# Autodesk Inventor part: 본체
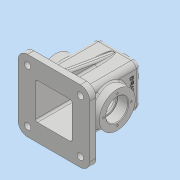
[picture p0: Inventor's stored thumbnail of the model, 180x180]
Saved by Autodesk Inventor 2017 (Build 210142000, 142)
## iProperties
Part Number: 본체
Material: 일반
Document SubType Name: Modeling
Designer: MRC
Density: 1 g/cm^3
Appearance: 기본값
Author: MRC
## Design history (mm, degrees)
sketch "스케치1"
  geometry: L1 (-34, 34)-(34, 34); L2 (34, 34)-(34, -34); L3 (34, -34)-(-34, -34); L4 (-34, -34)-(-34, 34); L5 (-34, 34)-(34, -34); L6 (34, 34)-(-34, -34); 1 further point
  constraints: 12 end point, 2 midpoint, 2 parallel, 1 horizontal, 1 perpendicular
  dimensions: "d0" = 68 distance of L2.end L3.end; "d1" = 68 distance of L3.end L1.start
extrude "돌출1" new body sketch "스케치1" distance "d2" = 53; taper "d4" = 0 deg; dims "d3" = 52, "d5" = 0
fillet "모깎기1" dims "d6" = 8
feature "쉘1" dims "d7" = 5
node "작업 평면2"
sketch "스케치3"
  geometry: C1 r 28.5 at (-26, 52); 1 further point
  constraints: 1 centre point, 1 coincident
  dimensions: "d10" = 57 diameter of C1
extrude "돌출2" join sketch "스케치3" stored distance "d11" = 53; taper "d12" = 0 deg
hole "구멍1" diameter "d15" = 30; stored, may be unused: countersink angle "d19" = 90 deg, drill point angle "d21" = 118 deg; dims "d13" = 10, "d14" = 10, "d16" = 6, "d17" = 35, "d18" = 17, "d20" = 8
sketch "스케치4"
  geometry: C1 r 17.5 at (0, 0) reference; 1 further point
  constraints: 1 vertical alignment
  dimensions: "d22" = 22 distance of point (0, 22) C1.centre
hole "구멍2" sketch "스케치4" at (0, 22) diameter "d23" = 3.242; stored, may be unused: countersink angle "d27" = 90 deg, drill point angle "d29" = 118 deg; dims "d24" = 8, "d25" = 35, "d26" = 17, "d28" = 10
sketch "스케치6"
  geometry: L1 (-26, -34)-(26, -34) reference; L2 (34, -26)-(34, 26) reference; L3 (26, 34)-(-26, 34) reference; L4 (-34, 26)-(-34, -26) reference; L5 (-57, -57)-(57, -57); L6 (57, -57)-(57, 57); L7 (57, 57)-(-57, 57); L8 (-57, 57)-(-57, -57); L9 (-57, -57)-(57, 57); L10 (57, -57)-(-57, 57); A1 r 8 centre (-26, -26) between (-34, -26) and (-26, -34) reference; A2 r 8 centre (26, -26) between (26, -34) and (34, -26) reference; A3 r 8 centre (26, 26) between (34, 26) and (26, 34) reference; A4 r 8 centre (-26, 26) between (-26, 34) and (-34, 26) reference; 1 further point
  constraints: 12 end point, 2 midpoint, 2 parallel, 1 horizontal, 1 perpendicular
  dimensions: "d34" = 114 distance of L7.end L6.end; "d35" = 114 distance of L5.end L6.end
extrude "돌출3" join sketch "스케치6" distance "d36" = 10; taper "d37" = 0 deg
fillet "모깎기2" dims "d38" = 15
sketch "스케치7"
  geometry: A1 r 15 centre (-42, 42) between (-42, 57) and (-57, 42) reference; A2 r 15 centre (42, 42) between (57, 42) and (42, 57) reference; 3 further points
  constraints: 2 coincident
  dimensions: "d39" = 84 distance of point (-42, 42) point (42, 42); "d40" = 42 horizontal distance of point (42, 42) point (0, 0) (= 0.5 x d39)
hole "구멍3" sketch "스케치7" at (42, 42), (-42, 42) diameter "d41" = 10; stored, may be unused: countersink angle "d45" = 90 deg, drill point angle "d47" = 118 deg; dims "d42" = 10, "d43" = 18, "d44" = 2, "d46" = 10
node "작업 평면3"
sketch "스케치8"
  geometry: C1 r 20 at (0, 0); 1 further point
  constraints: 1 centre point, 1 coincident
  dimensions: "d49" = 40 diameter of C1
extrude "돌출4" join sketch "스케치8" stored distance "d50" = 10; taper "d51" = 8 deg
hole "구멍4" diameter "d54" = 22.835; stored, may be unused: countersink angle "d58" = 90 deg, drill point angle "d60" = 118 deg; dims "d52" = 10, "d53" = 10, "d55" = 50, "d56" = 18, "d57" = 2, "d59" = 59.3
sketch "스케치9"
  geometry: L1 (-7, 42.829)-(-42, 49); L2 (-42, 57)-(-52, 57) reference; L3 (-42, 51)-(-42, 33) reference; 1 further point
  constraints: 2 end point, 1 point on line
  dimensions: "d61" = 10 deg angle of L2 L1; "d62" = 8 distance from line of L2 L1.end
feature "리브1" sketch "스케치9" dims "d63" = 1, "d64" = 10, "d65" = 0, "d66" = 0, "d67" = 1, "d68" = 1
fillet "모깎기3" dims "d69" = 3
fillet "모깎기4" dims "d70" = 3
chamfer "모따기1" distance "d71" = 1; stored, may be unused: second distance "d72" = 2, angle "d73" = 45 deg
sketch "스케치10"
  geometry: L1 (6, 18)-(46, 18) reference; L2 (-8, 0)-(0, 0) reference; 1 further point
  constraints: 1 other
  dimensions: "d74" = 25 distance from line of point (26, -7) L1; "d75" = 34 horizontal distance of point (26, -7) L2.start
feature "엠보싱1" sketch "스케치10" dims "d0" = 68, "d1" = 68, "d76" = 0.5, "d77" = 0
fillet "모깎기5" dims "d78" = 0.3
node "솔리드1"
pattern_circular "원형 패턴1" dims angle "d31" = 360 deg
mirror "미러1"
mirror "미러2"
mirror "미러3"
other parameters: "d9" = 15
